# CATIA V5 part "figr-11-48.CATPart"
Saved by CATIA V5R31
Part number: Part1
Bounding box of the stored display mesh (mm): x -270.607 to 0, y -223.278 to 0, z -13.562 to 46.691
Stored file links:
  D:\PROJECTS\Project 2021\US EDITION\CATIA V5 6R 2021\Resources\Part Files\c11_catia_v5_6r2021_prt\figr-11-48.CATPart
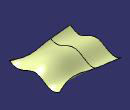
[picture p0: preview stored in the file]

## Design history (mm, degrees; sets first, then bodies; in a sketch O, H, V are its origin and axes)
Set1
  Sweep1: type Unspec, Profile Sketch2, Guide Sketch1
  Extrapol1: ToExtrapol edge of Sweep1, Support Sweep1, Length 100
Body1 (main body)
  Sketch1 on yz-plane, origin (0, 0, 0), H (0, 1, 0), V (0, 0, 1)
    spline S1 through (0, 0) (-40, -10) (-100, 20) (-170, 0) (-220, 10)
    point P1 (0, 0)
    coincidence: P1 O
  Sketch2 on zx-plane, origin (0, 0, 0), H (-1, 0, 0), V (0, 0, 1)
    spline S1 through (0, 0) (60, 30) (121.1814, 19.9844) (171.1814, 9.9844)
    point P1 (0, 0)
    coincidence: P1 O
